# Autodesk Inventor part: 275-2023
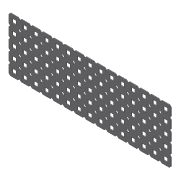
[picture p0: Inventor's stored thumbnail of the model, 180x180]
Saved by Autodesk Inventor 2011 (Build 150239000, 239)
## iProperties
Company: Autodesk Inc.
Created: 2005-08
Part Number: 275-2023
Document SubType Name: Sheet Metal
Designer: Autodesk Inc.
Density: 1 g/cm^3
Sheet Metal Rule: Default
Catalog Web Link: http://www.vexrobotics.com/products/accessories/structure/plate.html
Description: http://www.vexrobotics.com/products/accessories/structure/plate.html
Vendor: Innovation First, Inc.
Author: Autodesk Inc.
Title: VEX Robotics Kit of Parts
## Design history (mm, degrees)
node "Face1"
  sketch "Sketch1"
    geometry: L1 (-15.07, 9.738)-(-23.96, 9.738); L2 (-25.865, 7.833)-(-25.865, -1.057); L3 (-23.96, -2.962)-(-15.07, -2.962); L4 (-13.165, -1.057)-(-13.165, 7.833); L5 (-25.865, 7.833)-(-23.96, 9.738); L6 (-25.865, -1.057)-(-23.96, -2.962); L7 (-15.07, -2.962)-(-13.165, -1.057); L8 (-13.165, 7.833)-(-15.07, 9.738); L9 (-21.801, 5.674)-(-17.229, 5.674); L10 (-17.229, 5.674)-(-17.229, 1.102); L11 (-17.229, 1.102)-(-21.801, 1.102); L12 (-21.801, 1.102)-(-21.801, 5.674); 4 further points
    constraints: 24 end point, 8 point on line, 4 parallel, 2 horizontal, 2 perpendicular
    dimensions: "d0" = 12.7 distance of point (-25.865, 9.738) point (-25.865, -2.962); "d1" = 12.7 distance of point (-13.165, 9.738) point (-25.865, 9.738); "d2" = 1.905 distance of L2.start point (-25.865, 9.738); "d3" = 1.905 distance of L1.end point (-25.865, 9.738) (= d2); "d4" = 1.905 distance of L2.end point (-25.865, -2.962) (= d2); "d5" = 1.905 distance of L3.start point (-25.865, -2.962) (= d4); "d6" = 1.905 distance of L3.end point (-13.165, -2.962) (= d2); "d7" = 1.905 distance of L4.start point (-13.165, -2.962) (= d6); "d8" = 1.905 distance of L4.end point (-13.165, 9.738) (= d2); "d9" = 1.905 distance of L1.start point (-13.165, 9.738) (= d8); "d10" = 4.572 distance of L11.end L9.start; "d11" = 4.572 distance of L10.end L11.end; "d12" = 4.064 distance between parallel lines of L1 L9; "d13" = 4.064 distance between parallel lines of L4 L10
body "Solid1"
pattern_linear "Rectangular Pattern1" dims "d17" = 12.7, "d23" = 12.7
face "Plate1" dims "Thickness" = 0.8509
other parameters: "BendRadius" = 0.8509 (= Thickness), "BendReliefWidth" = 0.8509 (= Thickness), "BendReliefDepth" = 0.42545 (= 0.5 x Thickness), "CornerReliefSize" = 3.4036 (= 4 x Thickness), "SeamGap" = 0.00508, "MinimumRemnant" = 1.7018 (= 2 x Thickness), "TransitionRadius" = 0.8509 (= BendRadius), "d14" = 0.8509 (= BendRadius), "JacobiRadiusSize" = 0.8509 (= Thickness), "GapSize" = 0.8509 (= Thickness)
